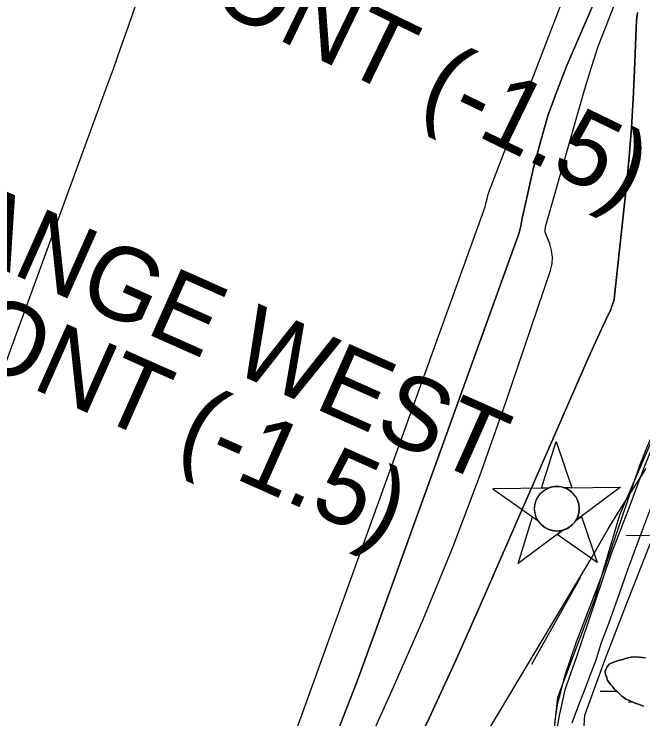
# Model space of a CAD drawing. Extents: x 3925854 to 3964121, y 224593 to 250589.
# Drawn here: x 3942841 to 3943702, y 235095 to 236061 of the extents above; entities that cross this region are included whole.
import ezdxf

# ---------------------------------------------------------------- set-up
doc = ezdxf.new("R2010")
doc.units = 0
for name, color, linetype in [('V-CHAN-NAID', 7, 'Continuous'), ('V-RIVR-EDGE', 7, 'Continuous'), ('V-RIVR-JETY', 7, 'Continuous'), ('V-RRAP-FSHR', 7, 'Continuous'), ('V-TOPO-DPTH', 7, 'Continuous'), ('V-TOPO-MAJR', 7, 'Continuous'), ('V-TOPO-MINR', 7, 'Continuous'), ('V-TOPO-SHOR', 7, 'Continuous'), ('V-WETL-SWMP', 7, 'Continuous')]:
    doc.layers.add(name, color=color, linetype=linetype)

msp = doc.modelspace()

# ---------------------------------------------------------------- linework, layer by layer
at = {"layer": 'V-CHAN-NAID'}
for points in [[(3943573.153, 235411.399), (3943563.567, 235411.28), (3943583.452, 235475.163), (3943604.915, 235411.792), (3943595.328, 235411.674), (3943593.74, 235412.221), (3943591.634, 235412.8), (3943589.585, 235413.211), (3943587.544, 235413.479), (3943586.375, 235413.57), (3943584.839, 235413.622), (3943583.118, 235413.586), (3943581.749, 235413.489), (3943579.847, 235413.251), (3943578.486, 235413.006), (3943576.71, 235412.587), (3943575.188, 235412.137), (3943574.163, 235411.786)], [(3943573.153, 235411.399), (3943496.666, 235410.451), (3943559.104, 235366.259), (3943557.954, 235368.146), (3943557.112, 235369.758), (3943556.249, 235371.71), (3943555.513, 235373.75), (3943555.123, 235375.065), (3943554.73, 235376.684), (3943554.458, 235378.124), (3943554.239, 235379.718), (3943554.096, 235381.452), (3943554.053, 235383.032), (3943554.12, 235385.108), (3943554.271, 235386.729), (3943554.62, 235388.939), (3943555.064, 235390.871), (3943555.63, 235392.77), (3943556.252, 235394.461), (3943556.948, 235396.063), (3943557.732, 235397.614), (3943558.759, 235399.371), (3943559.761, 235400.861), (3943560.736, 235402.149), (3943561.716, 235403.314), (3943562.998, 235404.677), (3943564.03, 235405.662), (3943565.72, 235407.092), (3943566.915, 235407.985), (3943568.58, 235409.088), (3943570.293, 235410.067), (3943571.725, 235410.779)], [(3943595.328, 235411.674), (3943671.816, 235412.62), (3943610.492, 235366.895), (3943611.374, 235368.402), (3943612.316, 235370.268), (3943613, 235371.866), (3943613.701, 235373.835), (3943614.211, 235375.63), (3943614.577, 235377.277), (3943614.899, 235379.294), (3943615.054, 235380.87), (3943615.135, 235383.078), (3943615.065, 235385.139), (3943614.834, 235387.355), (3943614.533, 235389.107), (3943613.999, 235391.329), (3943613.317, 235393.456), (3943612.529, 235395.423), (3943611.853, 235396.854), (3943610.809, 235398.75), (3943609.713, 235400.451), (3943608.467, 235402.129), (3943607.176, 235403.643), (3943605.877, 235404.984), (3943604.216, 235406.484), (3943602.446, 235407.861), (3943600.74, 235409.005), (3943598.831, 235410.1), (3943597.345, 235410.833)], [(3943610.492, 235366.895), (3943618.178, 235372.627), (3943639.64, 235309.256), (3943585.029, 235347.91), (3943592.716, 235353.641), (3943594.372, 235354.149), (3943595.973, 235354.74), (3943598.113, 235355.696), (3943599.83, 235356.614), (3943601.674, 235357.764), (3943603.389, 235359.01), (3943604.917, 235360.285), (3943606.181, 235361.477), (3943607.537, 235362.924), (3943608.713, 235364.349), (3943609.804, 235365.843)], [(3943592.716, 235353.641), (3943531.392, 235307.916), (3943551.277, 235371.798), (3943559.104, 235366.259), (3943559.757, 235365.308), (3943561.176, 235363.476), (3943562.417, 235362.084), (3943563.912, 235360.61), (3943565.325, 235359.386), (3943566.801, 235358.259), (3943568.223, 235357.299), (3943569.921, 235356.296), (3943571.652, 235355.419), (3943573.459, 235354.643), (3943574.915, 235354.115), (3943576.553, 235353.618), (3943578.79, 235353.097), (3943580.327, 235352.84), (3943582.357, 235352.623), (3943583.896, 235352.549), (3943585.757, 235352.563), (3943587.444, 235352.674), (3943589.15, 235352.883), (3943591.046, 235353.231)]]:
    msp.add_lwpolyline(points, close=True, dxfattribs=at)
msp.add_circle((3943584.593, 235383.082), 30.541, dxfattribs=at)
at = {"layer": 'V-RIVR-EDGE'}
msp.add_lwpolyline([(3944040.446, 236067.646), (3944007.385, 235995.227), (3943991.642, 235945.636), (3943960.942, 235890.535), (3943855.463, 235692.957), (3943812.956, 235631.558), (3943768.875, 235583.541), (3943727.155, 235505.612), (3943670.48, 235374.156), (3943636.632, 235260.018), (3943585.466, 235124.626), (3943579.956, 235075.035), (3943597.274, 234983.724), (3943619.314, 234871.947), (3943619.314, 234696.41), (3943605.932, 234579.123), (3943578.382, 234442.157)], dxfattribs=at)
at = {"layer": 'V-RIVR-JETY'}
for points in [[(3944064.786, 236104.334), (3944042.604, 236052.647), (3944009.232, 235982.349), (3943954.976, 235869.723), (3943928.492, 235817.704), (3943901.241, 235766.865), (3943884.044, 235737.39), (3943862.071, 235701.333), (3943830.114, 235649.385), (3943806.253, 235618.436), (3943781.247, 235589.453), (3943762.434, 235556.091), (3943739.648, 235517.701), (3943721.195, 235481.988), (3943702.208, 235435.338), (3943681.935, 235380.11), (3943659.284, 235322.565), (3943636.093, 235253.695)], [(3943667.822, 235259.137), (3943681.648, 235299.601), (3943698.266, 235344.327), (3943716.092, 235391.773)], [(3943605.776, 235089.554), (3943614.705, 235114.452), (3943621.576, 235131.557), (3943630.891, 235156.055), (3943638.171, 235174.718), (3943645.538, 235199.634), (3943656.456, 235227.239), (3943667.822, 235259.137)], [(3943636.093, 235253.695), (3943611.277, 235180.158), (3943595.436, 235135.03), (3943587.93, 235099.563), (3943582.437, 235068.37)]]:
    msp.add_lwpolyline(points, dxfattribs=at)
at = {"layer": 'V-RRAP-FSHR'}
msp.add_lwpolyline([(3943550.3, 234438.974), (3943580.758, 234512.837), (3943648.153, 234785.105), (3943648.444, 234864.923), (3943633.272, 234943.444), (3943617.876, 235021.948), (3943622.994, 235100.327), (3943650.171, 235175.566), (3943678.906, 235250.224), (3943708.387, 235324.593), (3943738.82, 235398.878), (3943769.606, 235472.399), (3943805.37, 235543.862), (3943853.205, 235607.915), (3943894.849, 235676.646), (3943933.18, 235746.524), (3943970.3, 235817.305), (3944005.82, 235888.983), (3944041.119, 235960.773), (3944076.417, 236032.566), (3944110.874, 236104.758)], dxfattribs=at)
at = {"layer": 'V-TOPO-DPTH'}
for points in [[(3943643.774, 236096.247), (3943598.444, 235990.468), (3943584.8, 235956.077), (3943572.427, 235921.273), (3943561.959, 235885.849), (3943552.762, 235850.011), (3943537.936, 235784.949), (3943537.143, 235781.324), (3943536.392, 235777.692), (3943535.705, 235774.047), (3943535.06, 235770.393), (3943534.349, 235766.759), (3943533.509, 235763.158), (3943532.475, 235759.609), (3943531.312, 235756.093), (3943335.29, 235213.251), (3943310.805, 235147.024), (3943285.653, 235081.057)], [(3943643.774, 236096.247), (3943598.444, 235990.468), (3943584.8, 235956.077), (3943572.427, 235921.273), (3943561.959, 235885.849), (3943552.762, 235850.011), (3943537.936, 235784.949), (3943537.143, 235781.324), (3943536.392, 235777.692), (3943535.705, 235774.047), (3943535.06, 235770.393), (3943534.349, 235766.759), (3943533.509, 235763.158), (3943532.475, 235759.609), (3943531.312, 235756.093), (3943335.29, 235213.251), (3943310.805, 235147.024), (3943285.653, 235081.057)], [(3943216.56, 234819.199), (3943359.149, 235134.282), (3943401.325, 235231.27), (3943441.563, 235329.023), (3943478.894, 235427.922), (3943514.288, 235527.585), (3943575.911, 235709.589), (3943577.945, 235718.793), (3943578.669, 235727.961), (3943577.426, 235737.072), (3943574.872, 235746.146), (3943569.473, 235759.537), (3943568.789, 235761.899), (3943568.423, 235764.278), (3943568.967, 235769.103), (3943622.026, 235955.368), (3943631.55, 235986.579), (3943641.839, 236017.519), (3943653.274, 236048.054), (3943665.475, 236078.318)], [(3943216.56, 234819.199), (3943359.149, 235134.282), (3943401.325, 235231.27), (3943441.563, 235329.023), (3943478.894, 235427.922), (3943514.288, 235527.585), (3943575.911, 235709.589), (3943577.945, 235718.793), (3943578.669, 235727.961), (3943577.426, 235737.072), (3943574.872, 235746.146), (3943569.473, 235759.537), (3943568.789, 235761.899), (3943568.423, 235764.278), (3943568.967, 235769.103), (3943622.026, 235955.368), (3943631.55, 235986.579), (3943641.839, 236017.519), (3943653.274, 236048.054), (3943665.475, 236078.318)], [(3943695.051, 236062.942), (3943693.854, 236052.029), (3943693.109, 236041.053), (3943691.02, 235983.895), (3943689.163, 235944.321), (3943686.759, 235904.786), (3943683.536, 235865.309), (3943679.767, 235825.871), (3943663.28, 235670.425), (3943663.169, 235669.564), (3943663.088, 235669.227), (3943663.037, 235669.062), (3943660.838, 235662.711), (3943659.627, 235659.394), (3943658.342, 235656.108), (3943656.946, 235652.867), (3943655.477, 235649.656), (3943648.095, 235634.217), (3943642.936, 235623.284), (3943637.853, 235612.316), (3943632.883, 235601.296), (3943627.989, 235590.242), (3943479.736, 235250.682), (3943445.061, 235173.135), (3943409.481, 235096.015), (3943372.545, 235019.535)]]:
    msp.add_lwpolyline(points, dxfattribs=at)
at = {"layer": 'V-TOPO-MAJR'}
for points in [[(3943007.385, 236072.895), (3942997.258, 236043.589), (3942987.009, 236014.327), (3942976.577, 235985.129), (3942966.023, 235955.975), (3942825.344, 235571.158)], [(3943160.398, 234892.777), (3943486.229, 235796.554), (3943486.748, 235798.602), (3943486.927, 235799.431), (3943487.026, 235799.843), (3943489.006, 235807.732), (3943490.178, 235812.063), (3943491.453, 235816.361), (3943492.885, 235820.609), (3943494.421, 235824.825), (3943575.92, 236036.421), (3943583.622, 236056.555), (3943591.261, 236076.712)]]:
    msp.add_lwpolyline(points, dxfattribs=at)
at = {"layer": 'V-TOPO-MINR'}
for points in [[(3943285.653, 235081.057), (3943310.805, 235147.024), (3943335.29, 235213.251), (3943531.312, 235756.093), (3943532.475, 235759.609), (3943533.509, 235763.158), (3943534.349, 235766.759), (3943535.06, 235770.393), (3943535.705, 235774.047), (3943536.392, 235777.692), (3943537.143, 235781.324), (3943537.936, 235784.949), (3943552.762, 235850.011), (3943561.959, 235885.849), (3943572.427, 235921.273), (3943584.8, 235956.077), (3943598.444, 235990.468), (3943643.774, 236096.247)], [(3943216.56, 234819.199), (3943359.149, 235134.282), (3943401.325, 235231.27), (3943441.563, 235329.023), (3943478.894, 235427.922), (3943514.288, 235527.585), (3943575.911, 235709.589), (3943577.945, 235718.793), (3943578.669, 235727.961), (3943577.426, 235737.072), (3943574.872, 235746.146), (3943569.473, 235759.537), (3943568.789, 235761.899), (3943568.423, 235764.278), (3943568.967, 235769.103), (3943622.026, 235955.368), (3943631.55, 235986.579), (3943641.839, 236017.519), (3943653.274, 236048.054), (3943665.475, 236078.318)], [(3943372.545, 235019.535), (3943409.481, 235096.015), (3943445.061, 235173.135), (3943479.736, 235250.682), (3943627.989, 235590.242), (3943632.883, 235601.296), (3943637.853, 235612.316), (3943642.936, 235623.284), (3943648.095, 235634.217), (3943655.477, 235649.656), (3943656.946, 235652.867), (3943658.342, 235656.108), (3943659.627, 235659.394), (3943660.838, 235662.711), (3943663.037, 235669.062), (3943663.088, 235669.227), (3943663.169, 235669.564), (3943663.28, 235670.425), (3943679.767, 235825.871), (3943683.536, 235865.309), (3943686.759, 235904.786), (3943689.163, 235944.321), (3943691.02, 235983.895), (3943693.109, 236041.053), (3943693.854, 236052.029), (3943695.051, 236062.942)], [(3942982.448, 233802.833), (3943295.161, 234752.419), (3943296.059, 234754.917), (3943297.381, 234756.189), (3943629.757, 235311.766), (3943642.011, 235333.225), (3943654.509, 235354.538), (3943667.373, 235375.633), (3943680.48, 235396.581), (3943707.06, 235438.26)], [(3943550.48, 235170.12), (3943617.462, 235289.798)]]:
    msp.add_lwpolyline(points, dxfattribs=at)
at = {"layer": 'V-TOPO-SHOR'}
msp.add_lwpolyline([(3943703.355, 235112.631), (3943699.503, 235114.067), (3943696.478, 235115.211), (3943693.449, 235116.082), (3943689.601, 235117.79), (3943686.027, 235119.219), (3943682.728, 235120.647), (3943678.881, 235122.355), (3943676.143, 235124.327), (3943673.682, 235126.293), (3943670.677, 235129.099), (3943667.679, 235132.179), (3943665.215, 235134.147), (3943663.034, 235136.388), (3943661.131, 235138.901), (3943658.406, 235141.7), (3943655.964, 235145.327), (3943654.072, 235148.391), (3943652.468, 235152.561), (3943651.405, 235155.891), (3943650.902, 235159.491), (3943651.498, 235162.801), (3943653.484, 235166.645), (3943656.015, 235169.928), (3943658.797, 235171.273), (3943662.69, 235172.879), (3943666.301, 235174.214), (3943670.188, 235175.546), (3943675.177, 235176.586), (3943678.785, 235177.643), (3943682.115, 235178.704), (3943686.273, 235179.478), (3943689.597, 235179.988), (3943692.912, 235179.943), (3943696.783, 235179.891), (3943701.475, 235179.277), (3943706.169, 235178.937)], dxfattribs=at)
at = {"layer": 'V-WETL-SWMP'}
for p, q in [((3943679.316, 235346.212), (3943711.311, 235346.794)), ((3943644.031, 235132.931), (3943666.232, 235133.335)), ((3943682.306, 235118.193), (3943688.319, 235118.303))]:
    msp.add_line(p, q, dxfattribs=at)
for points in [[(3944037.173, 236064.347), (3943962.314, 235901.421), (3943897.877, 235774.016), (3943869.547, 235722.147), (3943839.301, 235671.687), (3943821.806, 235644.829), (3943808.615, 235629.801), (3943799.632, 235619.416), (3943789.259, 235608.497), (3943782.8, 235600.843), (3943774.665, 235591.829), (3943767.063, 235581.425), (3943751.253, 235556.481), (3943738.486, 235531.772), (3943721.468, 235499.103), (3943707.205, 235465.845), (3943697.203, 235441.1), (3943650.601, 235303.783), (3943611.08, 235200.096), (3943594.686, 235151.94), (3943589.443, 235131.83), (3943584.79, 235114.478), (3943581.137, 235089.095)], [(3943706.169, 235178.938), (3943701.474, 235179.277), (3943696.783, 235179.892), (3943689.597, 235179.987), (3943686.273, 235179.478), (3943682.116, 235178.704), (3943678.785, 235177.643), (3943675.177, 235176.585), (3943670.188, 235175.545), (3943666.3, 235174.215), (3943662.689, 235172.88), (3943658.797, 235171.273), (3943656.015, 235169.928), (3943653.484, 235166.645), (3943651.498, 235162.801), (3943650.901, 235159.492), (3943651.406, 235155.891), (3943652.468, 235152.56), (3943654.071, 235148.392), (3943655.965, 235145.327), (3943658.405, 235141.701), (3943661.132, 235138.9), (3943663.034, 235136.387), (3943665.216, 235134.147), (3943667.678, 235132.179), (3943670.677, 235129.099), (3943673.681, 235126.294), (3943676.143, 235124.327), (3943678.881, 235122.355), (3943682.728, 235120.646), (3943686.027, 235119.22), (3943689.601, 235117.79), (3943693.449, 235116.081), (3943696.478, 235115.211), (3943699.503, 235114.066), (3943703.354, 235112.632)]]:
    msp.add_lwpolyline(points, dxfattribs=at)

# ---------------------------------------------------------------- texts
at = {"layer": 'V-CHAN-NAID'}
for s, rotation, p in [('HEAD RANGE FRONT (-1.5)', 334.125503, (3942116.053, 236553)), ('HEAD RANGE WEST', 336.034856, (3942292.578, 235947.449)), ('FRONT (-1.5)', 336.034856, (3942605.062, 235663.823))]:
    msp.add_text(s, height=100, rotation=rotation, dxfattribs=at).set_placement(p)

doc.saveas('drawing.dxf')
